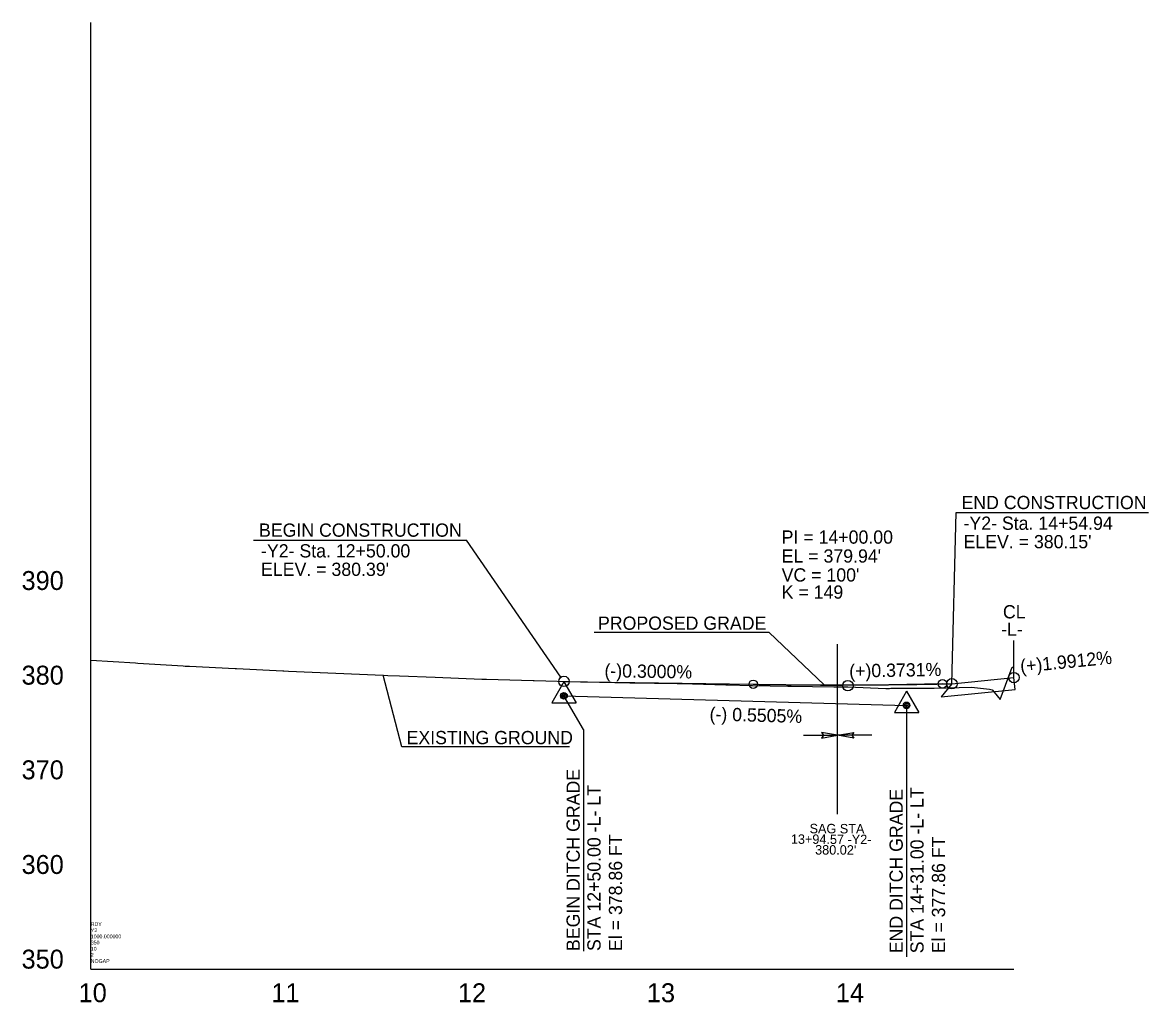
# Model space of a CAD drawing. Extents: x 1625686 to 1640492, y 1161393 to 1175642.
# Drawn here: x 1630168 to 1630763, y 1172143 to 1172661 of the extents above; entities that cross this region are included whole.
import ezdxf

# ---------------------------------------------------------------- set-up
doc = ezdxf.new("R2010")
doc.units = 0
for name, color, linetype in [('Exist Profile Cell', 7, 'Continuous'), ('Exist Vertical Profile Ground Line', 7, 'Continuous'), ('Exist Vertical Profile Horizontal Axis Label Major', 7, 'Continuous'), ('Exist Vertical Profile Vertical Axis Label', 7, 'Continuous'), ('Prop Plan Preparation Sag', 7, 'Continuous'), ('Prop Vertical Profile Curve Label', 7, 'Continuous'), ('Prop Vertical Profile Ditch Grade Left', 7, 'Continuous'), ('Prop Vertical Profile Ditch Grade Left Label', 7, 'Continuous'), ('Prop Vertical Profile Grade', 7, 'Continuous'), ('Prop Vertical Profile Grade Label', 7, 'Continuous'), ('Prop VPI Ditch Grade Left Label', 7, 'Continuous'), ('Prop VPI Label', 7, 'Continuous')]:
    doc.layers.add(name, color=color, linetype=linetype)

msp = doc.modelspace()

# ---------------------------------------------------------------- linework, layer by layer
at = {"layer": 'Exist Profile Cell'}
for q in [(1630204.31, 1172661.09), (1630692.01, 1172161.09), (1630204.31, 1172161.09)]:
    msp.add_line((1630204.31, 1172161.09), q, dxfattribs=at)
at = {"layer": 'Exist Vertical Profile Ground Line'}
msp.add_lwpolyline([(1630204.31, 1172324.26), (1630227.88, 1172322.81), (1630229.21, 1172322.7), (1630253.2, 1172321.23), (1630254.21, 1172321.15), (1630256.4, 1172321.03), (1630280.62, 1172319.87), (1630281.36, 1172319.84), (1630305.8, 1172318.67), (1630306.3, 1172318.64), (1630308.84, 1172318.52), (1630333.84, 1172317.41), (1630358.85, 1172316.29), (1630361.29, 1172316.18), (1630367.45, 1172315.95), (1630386.24, 1172315.22), (1630410.87, 1172314.27), (1630411.26, 1172314.26), (1630412.96, 1172314.19), (1630413.35, 1172314.18), (1630437.96, 1172313.5), (1630438.61, 1172313.48), (1630463.05, 1172312.81), (1630465.08, 1172312.75), (1630489.13, 1172312.36), (1630490.08, 1172312.35), (1630514.1, 1172311.97), (1630515.08, 1172311.96), (1630516.24, 1172311.94), (1630539.88, 1172311.28), (1630541.24, 1172311.25), (1630553.05, 1172310.92), (1630553.83, 1172310.9), (1630572.51, 1172310.54), (1630574.33, 1172310.5), (1630596.84, 1172310.2), (1630599.01, 1172310.18), (1630603.25, 1172310.12), (1630604.21, 1172310.12), (1630624.38, 1172309.33), (1630625.75, 1172309.34), (1630626.31, 1172309.35), (1630627.02, 1172309.4), (1630648.72, 1172309.5), (1630649.92, 1172309.55), (1630669.53, 1172310.08), (1630671.13, 1172309.83), (1630679.07, 1172309.03), (1630680.44, 1172308.54), (1630681.59, 1172307.45), (1630684.78, 1172303.54), (1630687.63, 1172311.03), (1630691.11, 1172320.6), (1630692.01, 1172320.65)], dxfattribs=at)
at = {"layer": 'Prop Plan Preparation Sag'}
for p, q in [((1630598.88, 1172242.85), (1630598.88, 1172332.8)), ((1630580.88, 1172284.57), (1630598.88, 1172284.57)), ((1630616.88, 1172284.57), (1630598.88, 1172284.57))]:
    msp.add_line(p, q, dxfattribs=at)
for points in [[(1630590.32, 1172283.15), (1630598.88, 1172284.57), (1630590.32, 1172286), (1630591.38, 1172284.57)], [(1630607.45, 1172283.15), (1630598.88, 1172284.57), (1630607.45, 1172286), (1630606.38, 1172284.57)]]:
    msp.add_lwpolyline(points, close=True, dxfattribs=at)
at = {"layer": 'Prop Vertical Profile Curve Label'}
msp.add_line((1630692.01, 1172315.08), (1630692.01, 1172334.73), dxfattribs=at)
for centre in [(1630554.31, 1172311.54), (1630654.31, 1172311.72)]:
    msp.add_circle(centre, 2.25, dxfattribs=at)
at = {"layer": 'Prop Vertical Profile Ditch Grade Left'}
msp.add_line((1630454.31, 1172305.37), (1630635.31, 1172300.39), dxfattribs=at)
at = {"layer": 'Prop Vertical Profile Grade'}
for p, q in [((1630454.31, 1172313.04), (1630554.31, 1172311.54)), ((1630654.31, 1172311.72), (1630659.25, 1172311.82)), ((1630659.25, 1172311.82), (1630692.01, 1172315.08))]:
    msp.add_line(p, q, dxfattribs=at)
msp.add_spline([(1630554.31, 1172311.54), (1630556.31, 1172311.51), (1630558.31, 1172311.48), (1630560.31, 1172311.46), (1630562.31, 1172311.43), (1630564.31, 1172311.41), (1630566.31, 1172311.38), (1630568.31, 1172311.36), (1630570.31, 1172311.34), (1630572.31, 1172311.32), (1630574.31, 1172311.31), (1630576.31, 1172311.29), (1630578.31, 1172311.28), (1630580.31, 1172311.26), (1630582.31, 1172311.25), (1630584.31, 1172311.24), (1630586.31, 1172311.23), (1630588.31, 1172311.22), (1630590.31, 1172311.22), (1630592.31, 1172311.21), (1630594.31, 1172311.21), (1630596.31, 1172311.21), (1630598.31, 1172311.21), (1630600.31, 1172311.21), (1630602.31, 1172311.21), (1630604.31, 1172311.21), (1630606.31, 1172311.22), (1630608.31, 1172311.22), (1630610.31, 1172311.23), (1630612.31, 1172311.24), (1630614.31, 1172311.25), (1630616.31, 1172311.26), (1630618.31, 1172311.27), (1630620.31, 1172311.28), (1630622.31, 1172311.3), (1630624.31, 1172311.31), (1630626.31, 1172311.33), (1630628.31, 1172311.35), (1630630.31, 1172311.37), (1630632.31, 1172311.39), (1630634.31, 1172311.42), (1630636.31, 1172311.44), (1630638.31, 1172311.47), (1630640.31, 1172311.49), (1630642.31, 1172311.52), (1630644.31, 1172311.55), (1630646.31, 1172311.58), (1630648.31, 1172311.62), (1630650.31, 1172311.65), (1630652.31, 1172311.69), (1630654.31, 1172311.72)], degree=3, dxfattribs=at)
at = {"layer": 'Prop VPI Ditch Grade Left Label'}
for p, q in [((1630454.31, 1172312.85), (1630447.86, 1172301.65)), ((1630454.31, 1172312.85), (1630460.81, 1172301.65)), ((1630635.31, 1172307.88), (1630628.86, 1172296.68)), ((1630635.31, 1172307.88), (1630641.81, 1172296.68)), ((1630447.86, 1172301.65), (1630460.81, 1172301.65)), ((1630464.65, 1172287.68), (1630454.31, 1172305.37)), ((1630635.31, 1172300.39), (1630635.31, 1172169.93)), ((1630628.86, 1172296.68), (1630641.81, 1172296.68)), ((1630635.31, 1172298.09), (1630635.31, 1172167.63)), ((1630464.65, 1172287.68), (1630464.65, 1172170.62))]:
    msp.add_line(p, q, dxfattribs=at)
for centre, radius in [((1630454.31, 1172305.37), 1.75), ((1630454.31, 1172305.37), 1.2), ((1630454.31, 1172305.37), 0.5), ((1630635.31, 1172300.39), 1.75), ((1630635.31, 1172300.39), 1.2), ((1630635.31, 1172300.39), 0.5)]:
    msp.add_circle(centre, radius, dxfattribs=at)
at = {"layer": 'Prop VPI Label'}
for p, q in [((1630659.29, 1172311.82), (1630661.47, 1172402.34)), ((1630661.47, 1172402.34), (1630763.11, 1172402.34)), ((1630290.35, 1172387.74), (1630402.83, 1172387.74)), ((1630452.65, 1172315.23), (1630402.83, 1172387.74)), ((1630562.78, 1172338.87), (1630470.23, 1172338.87)), ((1630562.78, 1172338.87), (1630591.7, 1172311.21)), ((1630368.63, 1172278.44), (1630358.85, 1172316.29)), ((1630654.31, 1172311.72), (1630607.06, 1172310.84)), ((1630659.29, 1172311.83), (1630653.57, 1172304.84)), ((1630692.65, 1172308.72), (1630692.01, 1172315.08)), ((1630554.31, 1172311.54), (1630601.56, 1172310.83)), ((1630653.57, 1172304.84), (1630692.65, 1172308.72)), ((1630457.23, 1172278.44), (1630368.63, 1172278.44))]:
    msp.add_line(p, q, dxfattribs=at)
for centre in [(1630692.01, 1172315.08), (1630454.31, 1172313.04), (1630604.31, 1172310.79), (1630659.25, 1172311.82)]:
    msp.add_circle(centre, 2.75, dxfattribs=at)

# ---------------------------------------------------------------- texts
at = {"layer": 'Exist Profile Cell'}
for s, p in [('Y2', (1630204.31, 1172180.59)), ('RDY', (1630204.31, 1172183.84)), ('350', (1630204.31, 1172174.09)), ('1000.000000', (1630204.31, 1172177.34)), ('2', (1630204.31, 1172167.59)), ('10', (1630204.31, 1172170.84)), ('NOGAP', (1630204.31, 1172164.34))]:
    msp.add_text(s, height=2, dxfattribs=at).set_placement(p)
at = {"layer": 'Exist Vertical Profile Horizontal Axis Label Major'}
for s, p in [('10', (1630197.9, 1172143.59)), ('11', (1630299.74, 1172143.59)), ('12', (1630398.29, 1172143.59)), ('13', (1630498.12, 1172143.59)), ('14', (1630597.96, 1172143.59))]:
    msp.add_text(s, height=10, dxfattribs=at).set_placement(p)
at = {"layer": 'Exist Vertical Profile Vertical Axis Label'}
for s, p in [('390', (1630167.75, 1172361.34)), ('380', (1630167.75, 1172311.34)), ('370', (1630167.75, 1172261.34)), ('360', (1630167.75, 1172211.34)), ('350', (1630167.75, 1172161.34))]:
    msp.add_text(s, height=10, dxfattribs=at).set_placement(p)
at = {"layer": 'Prop Plan Preparation Sag'}
for s, p in [('SAG STA', (1630584.05, 1172232.83)), ('13+94.57 -Y2-', (1630574.18, 1172227.27)), ("380.02'", (1630586.99, 1172221.6))]:
    msp.add_text(s, height=5, rotation=359.75466, dxfattribs=at).set_placement(p)
at = {"layer": 'Prop Vertical Profile Curve Label'}
for s, p in [("VC = 100'", (1630569.31, 1172365.79)), ('K = 149', (1630569.31, 1172356.74))]:
    msp.add_text(s, height=7, dxfattribs=at).set_placement(p)
at = {"layer": 'Prop Vertical Profile Ditch Grade Left Label'}
msp.add_text('(-) 0.5505%', height=7, rotation=358.42476, dxfattribs=at).set_placement((1630531.16, 1172292.42))
at = {"layer": 'Prop Vertical Profile Grade Label'}
for s, rotation, p in [('(+)1.9912%', 5.68556, (1630695.68, 1172317.56)), ('(-)0.3000%', 359.14063, (1630475.66, 1172315.25)), ('(+)0.3731%', 1.06883, (1630605.06, 1172315.04))]:
    msp.add_text(s, height=7, rotation=rotation, dxfattribs=at).set_placement(p)
at = {"layer": 'Prop VPI Ditch Grade Left Label'}
for s, p in [('BEGIN DITCH GRADE', (1630462.65, 1172170.62)), ('STA 12+50.00 -L- LT', (1630473.65, 1172170.62)), ('END DITCH GRADE', (1630633.31, 1172169.44)), ('END DITCH GRADE', (1630633.31, 1172169.44)), ('STA 14+31.00 -L- LT', (1630644.31, 1172169.44)), ('El = 378.86 FT', (1630485.03, 1172170.62)), ('El = 377.86 FT', (1630655.69, 1172169.44))]:
    msp.add_text(s, height=7, rotation=90, dxfattribs=at).set_placement(p)
at = {"layer": 'Prop VPI Label'}
for s, p in [('END CONSTRUCTION', (1630664.31, 1172404.06)), ('BEGIN CONSTRUCTION', (1630293.19, 1172389.46)), ('-Y2- Sta. 14+54.94', (1630665.39, 1172393.12)), ('PI = 14+00.00', (1630569.31, 1172385.79)), ("ELEV. = 380.15'", (1630665.39, 1172383.37)), ('-Y2- Sta. 12+50.00', (1630294.27, 1172378.52)), ("EL = 379.94'", (1630569.31, 1172375.79)), ("ELEV. = 380.39'", (1630294.27, 1172368.77)), ('CL', (1630686.21, 1172346.33)), ('PROPOSED GRADE', (1630472.28, 1172340.32)), ('-L-', (1630685.24, 1172337.16)), ('EXISTING GROUND', (1630371.15, 1172279.88))]:
    msp.add_text(s, height=7, dxfattribs=at).set_placement(p)

doc.saveas('drawing.dxf')
